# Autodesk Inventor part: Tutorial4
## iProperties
Shininess: 77.0
Length Units: 11269
Angle Units: 11279
Time Units: 11290
Mass Units: 11283
Length Display Precision: 3
Angle Display Precision: 2
Created: 2001-11
Part Number: Tutorial4
Document SubType Name: Modeling
Designer: Renu Muthoo
Density: 1 g/cm^3
Density: 0.0
Volumn: 0.0
Area: 0.0
PropertySet Name: Model Information
Control State: 0
Master: False
Checked Out: False
Author: Renu Muthoo
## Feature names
1. Extrusion1
2. Extrusion2
3. Extrusion3
4. Extrusion4
5. Extrusion5
6. Extrusion6
